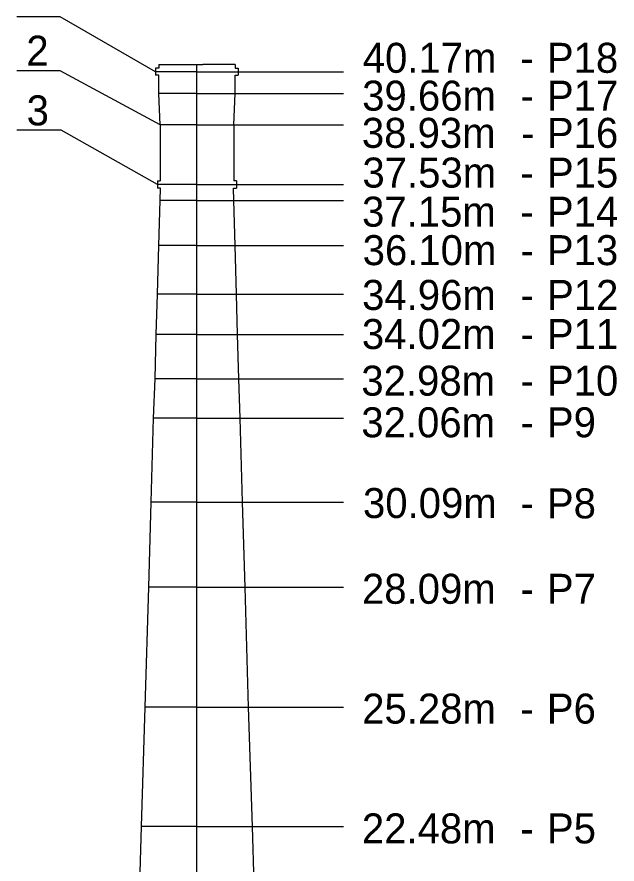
# Model space of a CAD drawing. Extents: x 138 to 264, y -75 to 121.
# Drawn here: x 169.88 to 176.89, y 66.47 to 76.36 of the extents above; entities that cross this region are included whole.
import ezdxf

# ---------------------------------------------------------------- set-up
doc = ezdxf.new("R2010")
doc.units = 0
doc.layers.add('Standard', color=7, linetype='Continuous')

msp = doc.modelspace()

# ---------------------------------------------------------------- linework, layer by layer
at = {"layer": 'Standard'}
for p, q in [((171.4977, 75.7618), (171.4977, 75.7196)), ((171.535, 75.7618), (171.4977, 75.7618)), ((171.535, 75.804), (171.535, 75.7618)), ((171.535, 75.804), (172.0501, 75.804)), ((171.9806, 55.7197), (171.9806, 75.804)), ((172.4261, 75.804), (172.0501, 75.804)), ((172.4261, 75.804), (172.4261, 75.7618)), ((172.4261, 75.7618), (172.4635, 75.7618)), ((172.4635, 75.7618), (172.4635, 75.7196)), ((171.9806, 75.7196), (171.4977, 75.7196)), ((171.4977, 75.7196), (171.4977, 75.6775)), ((171.535, 75.6775), (171.4977, 75.6775)), ((171.535, 75.4637), (171.535, 75.6775)), ((171.9806, 75.7196), (173.6908, 75.7196)), ((172.4261, 75.6775), (172.4635, 75.6775)), ((172.4261, 75.4637), (172.4261, 75.6775)), ((172.4635, 75.7196), (172.4635, 75.6775)), ((171.9806, 75.4637), (171.535, 75.4637)), ((171.55, 75.1008), (171.535, 75.4637)), ((171.9806, 75.4637), (173.6908, 75.4637)), ((172.4112, 75.1008), (172.4261, 75.4637)), ((171.9806, 75.1008), (171.55, 75.1008)), ((171.55, 75.1008), (171.55, 74.4469)), ((171.9806, 75.1008), (173.6908, 75.1008)), ((172.4112, 75.1008), (172.4112, 74.4469)), ((171.5201, 74.4469), (171.5201, 74.4029)), ((171.5201, 74.4469), (171.55, 74.4469)), ((172.4411, 74.4469), (172.4112, 74.4469)), ((172.4411, 74.4469), (172.4411, 74.4029)), ((171.9806, 74.4029), (171.5201, 74.4029)), ((171.5201, 74.4029), (171.5201, 74.3589)), ((171.5541, 74.3589), (171.5201, 74.3589)), ((171.55, 74.2152), (171.5541, 74.3589)), ((171.9806, 74.4029), (173.6908, 74.4029)), ((172.4112, 74.2152), (172.4071, 74.3589)), ((172.4071, 74.3589), (172.4411, 74.3589)), ((172.4411, 74.4029), (172.4411, 74.3589)), ((171.535, 73.6896), (171.55, 74.2152)), ((171.9806, 74.2152), (171.55, 74.2152)), ((171.9806, 74.2152), (173.6908, 74.2152)), ((172.4261, 73.6896), (172.4112, 74.2152)), ((171.5201, 73.1216), (171.535, 73.6896)), ((171.9806, 73.6896), (171.535, 73.6896)), ((171.9806, 73.6896), (173.6908, 73.6896)), ((172.4411, 73.1216), (172.4261, 73.6896)), ((171.5052, 72.6541), (171.5201, 73.1216)), ((171.9806, 73.1216), (171.5201, 73.1216)), ((171.9806, 73.1216), (173.6908, 73.1216)), ((172.456, 72.6541), (172.4411, 73.1216)), ((171.4927, 72.1369), (171.5052, 72.6541)), ((171.9806, 72.6541), (171.5052, 72.6541)), ((171.9806, 72.6541), (173.6908, 72.6541)), ((172.4684, 72.1369), (172.456, 72.6541)), ((171.4753, 71.6779), (171.4927, 72.1369)), ((171.9806, 72.1369), (171.4927, 72.1369)), ((171.9806, 72.1369), (173.6908, 72.1369)), ((172.4859, 71.6779), (172.4684, 72.1369)), ((171.4479, 70.6972), (171.4753, 71.6779)), ((171.9806, 71.6779), (171.4753, 71.6779)), ((171.9806, 71.6779), (173.6908, 71.6779)), ((172.5132, 70.6972), (172.4859, 71.6779)), ((171.4181, 69.7041), (171.4479, 70.6972)), ((171.9806, 70.6972), (171.4479, 70.6972)), ((171.9806, 70.6972), (173.6908, 70.6972)), ((172.5431, 69.7041), (172.5132, 70.6972)), ((171.3782, 68.3018), (171.4181, 69.7041)), ((171.9806, 69.7041), (171.4181, 69.7041)), ((171.9806, 69.7041), (173.6908, 69.7041)), ((172.5829, 68.3018), (172.5431, 69.7041)), ((171.3334, 66.9109), (171.3782, 68.3018)), ((171.9806, 68.3018), (171.3782, 68.3018)), ((171.9806, 68.3018), (173.6908, 68.3018)), ((172.6277, 66.9109), (172.5829, 68.3018)), ((171.2911, 65.5519), (171.3334, 66.9109)), ((171.9806, 66.9109), (171.3334, 66.9109)), ((171.9806, 66.9109), (173.6908, 66.9109)), ((172.67, 65.5519), (172.6277, 66.9109))]:
    msp.add_line(p, q, dxfattribs=at)
for points in [[(171.4977, 75.7196), (170.3835, 76.3588), (169.8792, 76.3588)], [(171.55, 75.1008), (170.3839, 75.7318), (169.8792, 75.7318)], [(171.5201, 74.4029), (170.3958, 75.039), (169.8792, 75.039)]]:
    msp.add_lwpolyline(points, dxfattribs=at)

# ---------------------------------------------------------------- texts
for s, p in [('2', (169.9888, 75.7903)), ('40.17m', (173.9167, 75.7069)), ('P18', (176.0668, 75.7069)), ('-', (175.7561, 75.7069)), ('39.66m', (173.9102, 75.2653)), ('P17', (176.0671, 75.2653)), ('3', (169.9923, 75.0931)), ('-', (175.7593, 75.2653)), ('38.93m', (173.9066, 74.8311)), ('P16', (176.0669, 74.8311)), ('-', (175.7657, 74.8311)), ('37.53m', (173.913, 74.3674)), ('P15', (176.0672, 74.3674)), ('-', (175.7561, 74.3674)), ('37.15m', (173.9086, 73.9111)), ('P14', (176.0669, 73.9111)), ('-', (175.7561, 73.9111)), ('36.10m', (173.9159, 73.4621)), ('P13', (176.0666, 73.4621)), ('-', (175.7593, 73.4621)), ('34.96m', (173.9089, 72.9396)), ('P12', (176.0687, 72.9396)), ('-', (175.7593, 72.9396)), ('34.02m', (173.9066, 72.4833)), ('P11', (176.0667, 72.4833)), ('-', (175.7593, 72.4833)), ('32.98m', (173.9002, 71.9386)), ('P10', (176.067, 71.9386)), ('-', (175.7593, 71.9386)), ('32.06m', (173.9002, 71.4529)), ('P9', (176.0669, 71.4529)), ('-', (175.7593, 71.4529)), ('30.09m', (173.9194, 70.5108)), ('P8', (176.0669, 70.5068)), ('-', (175.7593, 70.5108)), ('28.09m', (173.9078, 69.5099)), ('P7', (176.0666, 69.5099)), ('-', (175.7593, 69.5099)), ('25.28m', (173.91, 68.1115)), ('P6', (176.0661, 68.1115)), ('-', (175.7561, 68.1115)), ('22.48m', (173.9066, 66.7131)), ('P5', (176.0673, 66.7131)), ('-', (175.7561, 66.7131))]:
    msp.add_text(s, height=0.35, dxfattribs=at).set_placement(p)

doc.saveas('drawing.dxf')
